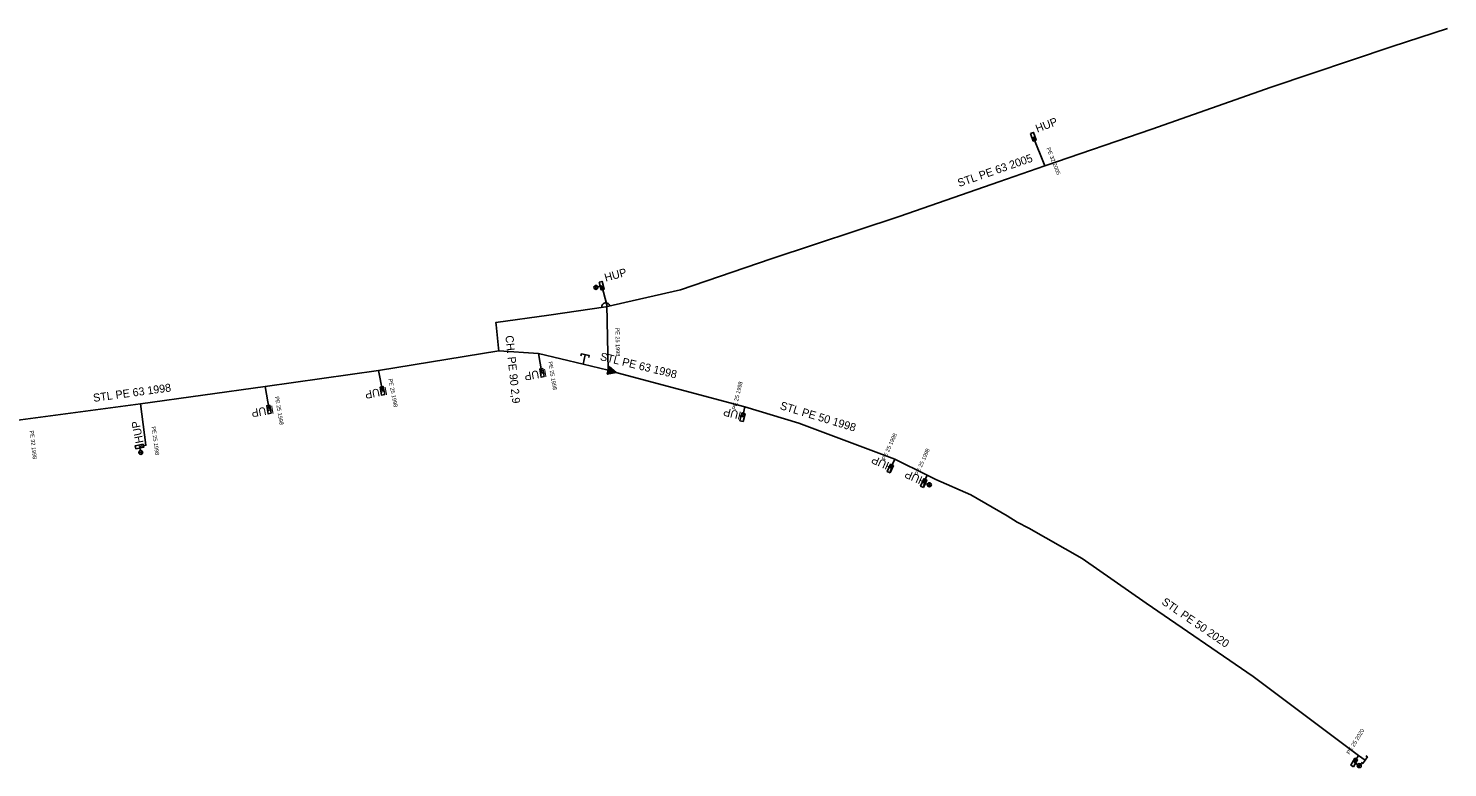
# Model space of a CAD drawing. Extents: x -741240 to -740302, y -1028024 to -1027535.
# Drawn here: x -740479 to -740301.6, y -1027837.1 to -1027744.7 of the extents above; entities that cross this region are included whole.
import ezdxf

# ---------------------------------------------------------------- set-up
doc = ezdxf.new("R2010")
doc.units = 0
for name, color, linetype in [('ST OP Chráni_ka - provoz', 7, 'Continuous'), ('ST Úsek p_ípojky - provoz', 7, 'Continuous'), ('ST Úsek plynovodu - provoz', 7, 'Continuous'), ('ST_HUP_22_23_popis', 7, 'Continuous'), ('Vrstva 1', 7, 'Continuous')]:
    doc.layers.add(name, color=color, linetype=linetype)

msp = doc.modelspace()

# ---------------------------------------------------------------- linework, layer by layer
at = {"layer": 'ST OP Chráni_ka - provoz'}
msp.add_lwpolyline([(-740420.22, -1027784.66), (-740420.52, -1027781.76)], dxfattribs=at)
at = {"layer": 'ST Úsek p_ípojky - provoz'}
for points in [[(-740351.96, -1027761.86), (-740353.38, -1027758.21)], [(-740406.51, -1027787.43), (-740406.67, -1027779.22), (-740407.33, -1027776.85)], [(-740415.22, -1027785.34), (-740414.8, -1027787.74)], [(-740435.23, -1027787.47), (-740434.73, -1027789.99)], [(-740449.4, -1027789.47), (-740448.91, -1027792.33)], [(-740464.98, -1027791.6), (-740464.29, -1027796.81), (-740465.09, -1027796.96)], [(-740389.42, -1027792), (-740389.73, -1027793.29)], [(-740370.71, -1027798.53), (-740371.25, -1027799.72)], [(-740366.65, -1027800.55), (-740367.09, -1027801.53)], [(-740312.74, -1027835.6), (-740313.28, -1027836.48)]]:
    msp.add_lwpolyline(points, dxfattribs=at)
at = {"layer": 'ST Úsek plynovodu - provoz'}
for points in [[(-740420.2, -1027785.01), (-740420.22, -1027784.66), (-740420.52, -1027781.76), (-740420.57, -1027781.45), (-740413.95, -1027780.54), (-740406.82, -1027779.47), (-740397.5, -1027777.36), (-740386.14, -1027773.5), (-740370.02, -1027768.13), (-740357.7, -1027763.85), (-740351.96, -1027761.86), (-740338.57, -1027757.27), (-740323.64, -1027752.03), (-740308.52, -1027746.91), (-740301.6, -1027744.66)], [(-740521.37, -1027798.02), (-740509.44, -1027797.15), (-740504.39, -1027796.76), (-740487.66, -1027794.54), (-740481.34, -1027793.85), (-740479.98, -1027793.64), (-740464.98, -1027791.6), (-740449.4, -1027789.47), (-740435.23, -1027787.47), (-740420.2, -1027785.01)], [(-740420.2, -1027785.01), (-740415.22, -1027785.34), (-740409.64, -1027786.67)], [(-740409.64, -1027786.67), (-740409.38, -1027785.48)], [(-740409.64, -1027786.67), (-740406.51, -1027787.43), (-740406.03, -1027787.56)], [(-740406.03, -1027787.56), (-740389.42, -1027792), (-740382.7, -1027794.04), (-740370.71, -1027798.53), (-740366.65, -1027800.55), (-740365.57, -1027801.08)], [(-740365.57, -1027801.08), (-740361.2, -1027803.02), (-740356.67, -1027805.62), (-740355.38, -1027806.41), (-740353.94, -1027807.18), (-740347.27, -1027810.95), (-740339.29, -1027816.54), (-740325.92, -1027825.74), (-740316.07, -1027833.11), (-740312.74, -1027835.6), (-740311.91, -1027836.2)]]:
    msp.add_lwpolyline(points, dxfattribs=at)
at = {"layer": 'Vrstva 1'}
for p, q in [((-740407.33, -1027776.85), (-740407.81, -1027776.99)), ((-740465.09, -1027796.96), (-740464.99, -1027797.45)), ((-740367.09, -1027801.53), (-740366.61, -1027801.68)), ((-740313.28, -1027836.48), (-740312.85, -1027836.74))]:
    msp.add_line(p, q, dxfattribs=at)
for points in [[(-740353.75, -1027757.81), (-740353.37, -1027757.67), (-740353.01, -1027758.61), (-740353.39, -1027758.75)], [(-740407.66, -1027776.42), (-740407.27, -1027776.31), (-740407, -1027777.28), (-740407.39, -1027777.38)], [(-740414.52, -1027788.2), (-740414.91, -1027788.27), (-740415.08, -1027787.28), (-740414.69, -1027787.21)], [(-740406.38, -1027786.95), (-740406.64, -1027787.91), (-740405.54, -1027787.69)], [(-740406.5, -1027787.78), (-740405.76, -1027787.63), (-740406.33, -1027787.13)], [(-740405.98, -1027787.57), (-740406.27, -1027787.31), (-740406.36, -1027787.65)], [(-740434.44, -1027790.44), (-740434.83, -1027790.52), (-740435.02, -1027789.54), (-740434.63, -1027789.46)], [(-740448.63, -1027792.79), (-740449.02, -1027792.86), (-740449.19, -1027791.87), (-740448.8, -1027791.8)], [(-740389.66, -1027793.82), (-740390.05, -1027793.73), (-740389.8, -1027792.76), (-740389.41, -1027792.85)], [(-740465.54, -1027797.25), (-740465.62, -1027796.86), (-740464.64, -1027796.67), (-740464.56, -1027797.06)], [(-740371.27, -1027800.26), (-740371.64, -1027800.1), (-740371.23, -1027799.18), (-740370.86, -1027799.34)], [(-740367.11, -1027802.07), (-740367.48, -1027801.9), (-740367.07, -1027800.99), (-740366.7, -1027801.15)], [(-740313.37, -1027837.01), (-740313.71, -1027836.8), (-740313.19, -1027835.95), (-740312.85, -1027836.16)]]:
    msp.add_lwpolyline(points, close=True, dxfattribs=at)
for points in [[(-740409.92, -1027785.62), (-740409.87, -1027785.38), (-740408.89, -1027785.58), (-740408.94, -1027785.83)], [(-740311.82, -1027835.65), (-740311.62, -1027835.79), (-740312.2, -1027836.61), (-740312.41, -1027836.46)]]:
    msp.add_lwpolyline(points, dxfattribs=at)
for centre, radius in [((-740408.05, -1027777.06), 0.249), ((-740408.07, -1027776.96), 0.0614), ((-740408.01, -1027777.16), 0.0614), ((-740464.94, -1027797.7), 0.249), ((-740465.05, -1027797.71), 0.0614), ((-740464.84, -1027797.67), 0.0614), ((-740366.37, -1027801.75), 0.249), ((-740366.35, -1027801.64), 0.0614), ((-740366.41, -1027801.84), 0.0614), ((-740312.64, -1027836.87), 0.249), ((-740312.7, -1027836.95), 0.0614), ((-740312.59, -1027836.78), 0.0614)]:
    msp.add_circle(centre, radius, dxfattribs=at)
msp.add_arc((-740406.82, -1027779.47), 0.5, 11, 191, dxfattribs=at)

# ---------------------------------------------------------------- texts
at = {"layer": 'ST OP Chráni_ka - provoz'}
msp.add_text('CH. PE 90 2,9', height=1, rotation=275.9041, dxfattribs=at).set_placement((-740419.37, -1027783.11))
at = {"layer": 'ST Úsek p_ípojky - provoz'}
for s, rotation, p in [('PE 32 2005', 291.2581, (-740351.74, -1027759.67)), ('PE 25 1998', 271.1165, (-740405.61, -1027782.08)), ('PE 25 1998', 279.9303, (-740414.02, -1027786.37)), ('PE 25 1998', 281.2268, (-740434, -1027788.53)), ('PE 25 1998', 76.4774, (-740390.55, -1027792.41)), ('PE 25 1998', 279.722, (-740448.17, -1027790.73)), ('PE 25 1998', 277.5442, (-740463.59, -1027794.48)), ('PE 32 1998', 276.472, (-740478.82, -1027794.98)), ('PE 25 1998', 65.6323, (-740371.89, -1027798.71)), ('PE 25 1998', 65.8477, (-740367.78, -1027800.63)), ('PE 25 2020', 58.4652, (-740313.86, -1027835.52))]:
    msp.add_text(s, height=0.5, rotation=rotation, dxfattribs=at).set_placement(p)
at = {"layer": 'ST Úsek plynovodu - provoz'}
for s, rotation, p in [('STL PE 63 2005', 19.1574, (-740362.64, -1027764.51)), ('STL PE 63 1998', 346.3521, (-740407.6, -1027786.14)), ('STL PE 63 1998', 7.7447, (-740470.82, -1027791.38)), ('STL PE 50 1998', 343.1132, (-740385.12, -1027792.26)), ('STL PE 50 2020', 325.4678, (-740337.42, -1027816.61))]:
    msp.add_text(s, height=1, rotation=rotation, dxfattribs=at).set_placement(p)
at = {"layer": 'ST_HUP_22_23_popis'}
for rotation, p in [(21, (-740352.88, -1027757.71)), (15.53, (-740406.83, -1027776.35)), (190, (-740414.3, -1027787.24)), (191, (-740434.23, -1027789.49)), (190, (-740448.41, -1027791.83)), (166, (-740389.23, -1027792.79)), (101, (-740464.59, -1027796.46)), (156, (-740370.75, -1027799.22)), (156, (-740366.59, -1027801.03))]:
    msp.add_text('HUP', height=1, rotation=rotation, dxfattribs=at).set_placement(p)

doc.saveas('drawing.dxf')
